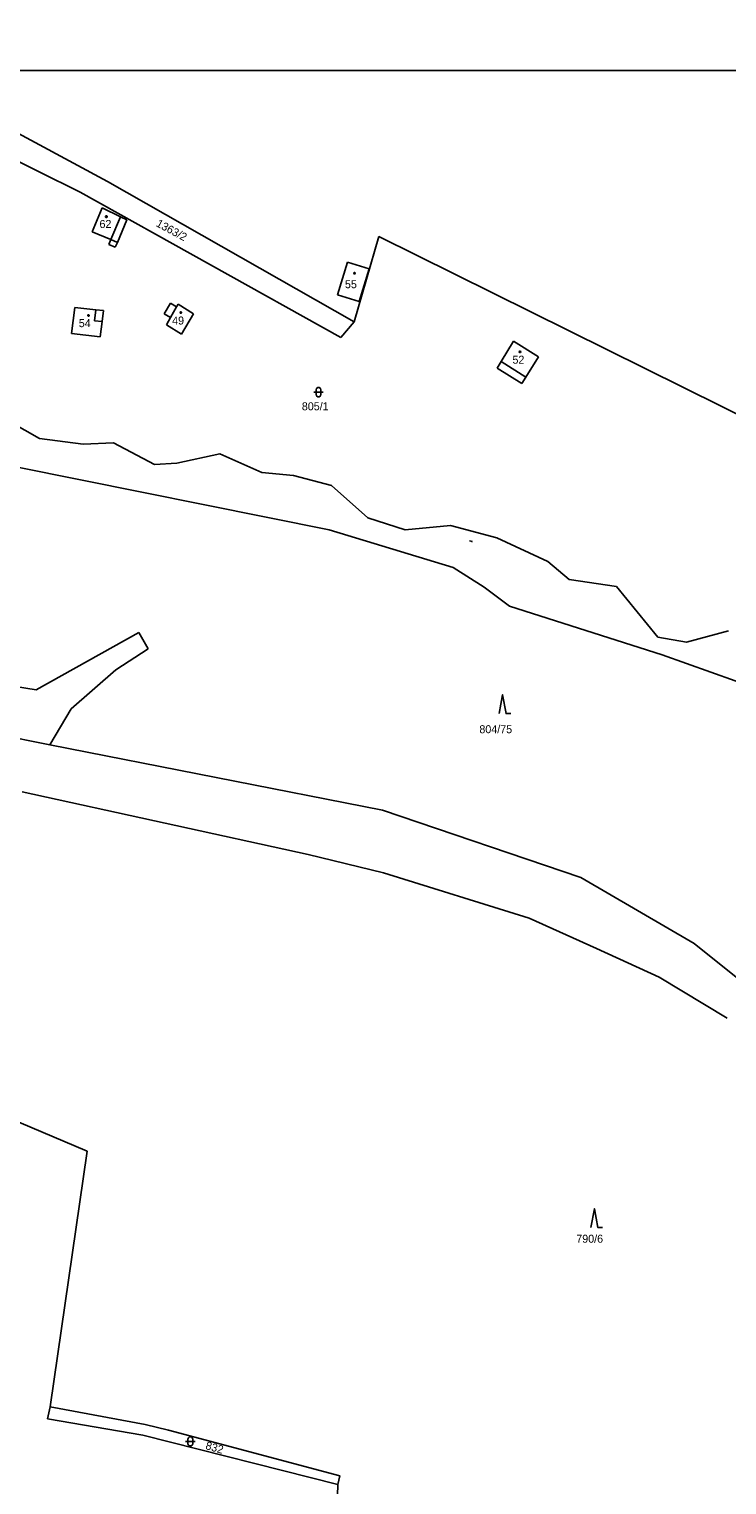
# Model space of a CAD drawing. Extents: x -852001 to -842497, y -1063614 to -1052182.
# Drawn here: x -843807.4 to -843659.2, y -1061876.7 to -1061567.4 of the extents above; entities that cross this region are included whole.
import ezdxf

# ---------------------------------------------------------------- set-up
doc = ezdxf.new("R2010")
doc.units = 0
for name, color, linetype in [('Default', 7, 'Continuous'), ('KN_HRANICE', 7, 'Continuous'), ('KN_KULTURY', 7, 'Continuous'), ('KN_PARCELY', 7, 'Continuous'), ('KN_SLUCKY', 7, 'Continuous'), ('LEGENDA', 7, 'Continuous')]:
    doc.layers.add(name, color=color, linetype=linetype)

# ---------------------------------------------------------------- blocks, each defined once
blk = doc.blocks.new('308')
at = {"layer": 'Default'}
blk.add_lwpolyline([(-0.75, 0), (0, 4), (0.75, 0), (1.75, 0)], dxfattribs=at)
blk = doc.blocks.new('316')
at = {"layer": 'Default'}
for points in [[(-1, 1), (0.27, 1), (1, 1)], [(-0.5, 1.5), (-0.4, 1.79), (-0.15, 1.97), (0.16, 1.97), (0.41, 1.79), (0.51, 1.5), (0.51, 0.5), (0.41, 0.21), (0.16, 0.03), (-0.15, 0.03), (-0.4, 0.21), (-0.5, 0.5), (-0.5, 1.5)]]:
    blk.add_lwpolyline(points, dxfattribs=at)
blk = doc.blocks.new('1060')
at = {"layer": 'Default'}
blk.add_line((-0.3, 0), (0.3, 0), dxfattribs=at)
blk.add_lwpolyline([(0.18, 0.04), (0.3, 0), (0.18, -0.04)], dxfattribs=at)
blk = doc.blocks.new('402')
at = {"layer": 'Default'}
blk.add_lwpolyline([(0.09, 0.15), (0.18, 0), (0.09, -0.15), (-0.09, -0.15), (-0.18, 0), (-0.09, 0.15), (0.09, 0.15)], dxfattribs=at)

msp = doc.modelspace()

# ---------------------------------------------------------------- linework, layer by layer
at = {"layer": 'KN_HRANICE'}
for p, q in [((-843790.75, -1061599.79), (-843825.88, -1061580.84)), ((-843790.75, -1061599.79), (-843825.88, -1061580.84)), ((-843796.57, -1061602.04), (-843829.99, -1061585.51)), ((-843796.57, -1061602.04), (-843829.99, -1061585.51)), ((-843738.36, -1061629.63), (-843790.75, -1061599.79)), ((-843738.36, -1061629.63), (-843790.75, -1061599.79)), ((-843741.22, -1061632.91), (-843796.57, -1061602.04)), ((-843741.22, -1061632.91), (-843796.57, -1061602.04)), ((-843791.86, -1061605.4), (-843794.02, -1061610.48)), ((-843791.86, -1061605.4), (-843794.02, -1061610.48)), ((-843787.99, -1061607.29), (-843791.86, -1061605.4)), ((-843787.99, -1061607.29), (-843791.86, -1061605.4)), ((-843786.62, -1061607.96), (-843787.99, -1061607.29)), ((-843786.62, -1061607.96), (-843787.99, -1061607.29)), ((-843794.02, -1061610.48), (-843790.06, -1061612.14)), ((-843794.02, -1061610.48), (-843790.06, -1061612.14)), ((-843788.66, -1061612.73), (-843786.62, -1061607.96)), ((-843788.66, -1061612.73), (-843786.62, -1061607.96)), ((-843790.49, -1061613.17), (-843790.06, -1061612.14)), ((-843790.49, -1061613.17), (-843790.06, -1061612.14)), ((-843789.09, -1061613.75), (-843790.49, -1061613.17)), ((-843789.09, -1061613.75), (-843790.49, -1061613.17)), ((-843788.66, -1061612.73), (-843789.09, -1061613.75)), ((-843788.66, -1061612.73), (-843789.09, -1061613.75)), ((-843738.36, -1061629.63), (-843733.15, -1061611.51)), ((-843738.36, -1061629.63), (-843733.15, -1061611.51)), ((-843733.15, -1061611.51), (-843581.94, -1061686.41)), ((-843733.15, -1061611.51), (-843581.94, -1061686.41)), ((-843739.78, -1061616.97), (-843741.91, -1061623.89)), ((-843739.78, -1061616.97), (-843741.91, -1061623.89)), ((-843735.17, -1061618.38), (-843739.78, -1061616.97)), ((-843735.17, -1061618.38), (-843739.78, -1061616.97)), ((-843737.3, -1061625.27), (-843735.17, -1061618.38)), ((-843737.3, -1061625.27), (-843735.17, -1061618.38)), ((-843778.7, -1061627.88), (-843777.35, -1061625.62)), ((-843778.7, -1061627.88), (-843777.35, -1061625.62)), ((-843777.35, -1061625.62), (-843776.08, -1061626.44)), ((-843777.35, -1061625.62), (-843776.08, -1061626.44)), ((-843776.08, -1061626.44), (-843775.77, -1061625.89)), ((-843776.08, -1061626.44), (-843775.77, -1061625.89)), ((-843772.46, -1061627.93), (-843775.77, -1061625.89)), ((-843772.46, -1061627.93), (-843775.77, -1061625.89)), ((-843741.91, -1061623.89), (-843737.3, -1061625.27)), ((-843741.91, -1061623.89), (-843737.3, -1061625.27)), ((-843797.7, -1061626.55), (-843798.4, -1061632.11)), ((-843797.7, -1061626.55), (-843798.4, -1061632.11)), ((-843793.25, -1061627.06), (-843797.7, -1061626.55)), ((-843793.25, -1061627.06), (-843797.7, -1061626.55)), ((-843791.58, -1061627.21), (-843793.25, -1061627.06)), ((-843791.58, -1061627.21), (-843793.25, -1061627.06)), ((-843792.32, -1061632.83), (-843791.89, -1061629.54)), ((-843792.32, -1061632.83), (-843791.89, -1061629.54)), ((-843791.89, -1061629.54), (-843791.58, -1061627.21)), ((-843791.89, -1061629.54), (-843791.58, -1061627.21)), ((-843777.36, -1061628.7), (-843778.7, -1061627.88)), ((-843777.36, -1061628.7), (-843778.7, -1061627.88)), ((-843778.23, -1061630.23), (-843777.36, -1061628.7)), ((-843778.23, -1061630.23), (-843777.36, -1061628.7)), ((-843775.02, -1061632.26), (-843772.46, -1061627.93)), ((-843775.02, -1061632.26), (-843772.46, -1061627.93)), ((-843798.4, -1061632.11), (-843792.32, -1061632.83)), ((-843798.4, -1061632.11), (-843792.32, -1061632.83)), ((-843778.23, -1061630.23), (-843775.02, -1061632.26)), ((-843778.23, -1061630.23), (-843775.02, -1061632.26)), ((-843738.36, -1061629.63), (-843741.22, -1061632.91)), ((-843738.36, -1061629.63), (-843741.22, -1061632.91)), ((-843704.5, -1061633.74), (-843707.14, -1061638.06)), ((-843704.5, -1061633.74), (-843707.14, -1061638.06)), ((-843699.21, -1061637.01), (-843704.5, -1061633.74)), ((-843699.21, -1061637.01), (-843704.5, -1061633.74)), ((-843707.14, -1061638.06), (-843708.01, -1061639.48)), ((-843707.14, -1061638.06), (-843708.01, -1061639.48)), ((-843699.21, -1061637.01), (-843701.9, -1061641.36)), ((-843699.21, -1061637.01), (-843701.9, -1061641.36)), ((-843708.01, -1061639.48), (-843702.77, -1061642.74)), ((-843708.01, -1061639.48), (-843702.77, -1061642.74)), ((-843701.9, -1061641.36), (-843702.77, -1061642.74)), ((-843701.9, -1061641.36), (-843702.77, -1061642.74)), ((-843743.69, -1061673.8), (-843809.84, -1061660.45)), ((-843743.69, -1061673.8), (-843809.84, -1061660.45)), ((-843717.35, -1061681.81), (-843743.69, -1061673.8)), ((-843717.35, -1061681.81), (-843743.69, -1061673.8)), ((-843710.75, -1061685.97), (-843717.35, -1061681.81)), ((-843710.75, -1061685.97), (-843717.35, -1061681.81)), ((-843705.34, -1061689.98), (-843710.75, -1061685.97)), ((-843705.34, -1061689.98), (-843710.75, -1061685.97)), ((-843672.91, -1061700.32), (-843705.34, -1061689.98)), ((-843672.91, -1061700.32), (-843705.34, -1061689.98)), ((-843805.91, -1061707.81), (-843784.1, -1061695.61)), ((-843805.91, -1061707.81), (-843784.1, -1061695.61)), ((-843784.1, -1061695.61), (-843782.09, -1061699.05)), ((-843784.1, -1061695.61), (-843782.09, -1061699.05)), ((-843782.09, -1061699.05), (-843788.98, -1061703.5)), ((-843782.09, -1061699.05), (-843788.98, -1061703.5)), ((-843610.42, -1061722.69), (-843672.91, -1061700.32)), ((-843610.42, -1061722.69), (-843672.91, -1061700.32)), ((-843788.98, -1061703.5), (-843798.45, -1061711.83)), ((-843788.98, -1061703.5), (-843798.45, -1061711.83)), ((-843818.83, -1061705.66), (-843805.91, -1061707.81)), ((-843818.83, -1061705.66), (-843805.91, -1061707.81)), ((-843798.45, -1061711.83), (-843803.02, -1061719.45)), ((-843798.45, -1061711.83), (-843803.02, -1061719.45)), ((-843803.02, -1061719.45), (-843833.57, -1061713.26)), ((-843803.02, -1061719.45), (-843833.57, -1061713.26)), ((-843732.34, -1061733.36), (-843803.02, -1061719.45)), ((-843732.34, -1061733.36), (-843803.02, -1061719.45)), ((-843808.89, -1061729.47), (-843748.15, -1061742.74)), ((-843808.89, -1061729.47), (-843748.15, -1061742.74)), ((-843690.18, -1061747.67), (-843732.34, -1061733.36)), ((-843690.18, -1061747.67), (-843732.34, -1061733.36)), ((-843748.15, -1061742.74), (-843732.13, -1061746.69)), ((-843748.15, -1061742.74), (-843732.13, -1061746.69)), ((-843732.13, -1061746.69), (-843701.21, -1061756.3)), ((-843732.13, -1061746.69), (-843701.21, -1061756.3)), ((-843666.11, -1061761.68), (-843690.18, -1061747.67)), ((-843666.11, -1061761.68), (-843690.18, -1061747.67)), ((-843701.21, -1061756.3), (-843686.91, -1061762.71)), ((-843701.21, -1061756.3), (-843686.91, -1061762.71)), ((-843652.18, -1061772.88), (-843666.11, -1061761.68)), ((-843652.18, -1061772.88), (-843666.11, -1061761.68)), ((-843686.91, -1061762.71), (-843673.54, -1061768.81)), ((-843686.91, -1061762.71), (-843673.54, -1061768.81)), ((-843673.54, -1061768.81), (-843659.13, -1061777.56)), ((-843673.54, -1061768.81), (-843659.13, -1061777.56)), ((-843795.06, -1061805.75), (-843847.5, -1061783.54)), ((-843795.06, -1061805.75), (-843847.5, -1061783.54)), ((-843802.94, -1061860.1), (-843795.06, -1061805.75)), ((-843802.94, -1061860.1), (-843795.06, -1061805.75)), ((-843802.94, -1061860.1), (-843803.53, -1061862.65)), ((-843802.94, -1061860.1), (-843803.53, -1061862.65)), ((-843782.76, -1061863.82), (-843802.94, -1061860.1)), ((-843782.76, -1061863.82), (-843802.94, -1061860.1)), ((-843803.53, -1061862.65), (-843783.27, -1061866.08)), ((-843803.53, -1061862.65), (-843783.27, -1061866.08)), ((-843777.81, -1061865.06), (-843782.76, -1061863.82)), ((-843777.81, -1061865.06), (-843782.76, -1061863.82)), ((-843783.27, -1061866.08), (-843741.79, -1061876.62)), ((-843783.27, -1061866.08), (-843741.79, -1061876.62)), ((-843741.39, -1061874.76), (-843777.81, -1061865.06)), ((-843741.39, -1061874.76), (-843777.81, -1061865.06)), ((-843741.79, -1061876.62), (-843743.62, -1061923)), ((-843741.79, -1061876.62), (-843743.62, -1061923)), ((-843741.39, -1061874.76), (-843741.79, -1061876.62)), ((-843741.39, -1061874.76), (-843741.79, -1061876.62))]:
    msp.add_line(p, q, dxfattribs=at)
at = {"layer": 'KN_SLUCKY'}
for p, q in [((-843787.99, -1061607.29), (-843790.06, -1061612.14)), ((-843787.99, -1061607.29), (-843790.06, -1061612.14)), ((-843790.06, -1061612.14), (-843788.66, -1061612.73)), ((-843790.06, -1061612.14), (-843788.66, -1061612.73)), ((-843776.08, -1061626.44), (-843777.36, -1061628.7)), ((-843776.08, -1061626.44), (-843777.36, -1061628.7)), ((-843793.53, -1061629.37), (-843793.25, -1061627.06)), ((-843793.53, -1061629.37), (-843793.25, -1061627.06)), ((-843791.89, -1061629.54), (-843793.53, -1061629.37)), ((-843791.89, -1061629.54), (-843793.53, -1061629.37)), ((-843701.9, -1061641.36), (-843707.14, -1061638.06)), ((-843701.9, -1061641.36), (-843707.14, -1061638.06)), ((-843811.41, -1061650.87), (-843805.17, -1061654.37)), ((-843811.41, -1061650.87), (-843805.17, -1061654.37)), ((-843805.17, -1061654.37), (-843795.89, -1061655.59)), ((-843805.17, -1061654.37), (-843795.89, -1061655.59)), ((-843795.89, -1061655.59), (-843789.5, -1061655.29)), ((-843795.89, -1061655.59), (-843789.5, -1061655.29)), ((-843789.5, -1061655.29), (-843780.76, -1061659.95)), ((-843789.5, -1061655.29), (-843780.76, -1061659.95)), ((-843780.76, -1061659.95), (-843776.04, -1061659.65)), ((-843780.76, -1061659.95), (-843776.04, -1061659.65)), ((-843776.04, -1061659.65), (-843766.91, -1061657.67)), ((-843776.04, -1061659.65), (-843766.91, -1061657.67)), ((-843766.91, -1061657.67), (-843757.94, -1061661.63)), ((-843766.91, -1061657.67), (-843757.94, -1061661.63)), ((-843757.94, -1061661.63), (-843751.24, -1061662.24)), ((-843757.94, -1061661.63), (-843751.24, -1061662.24)), ((-843751.24, -1061662.24), (-843743.18, -1061664.37)), ((-843751.24, -1061662.24), (-843743.18, -1061664.37)), ((-843743.18, -1061664.37), (-843735.42, -1061671.22)), ((-843743.18, -1061664.37), (-843735.42, -1061671.22)), ((-843735.42, -1061671.22), (-843727.51, -1061673.81)), ((-843735.42, -1061671.22), (-843727.51, -1061673.81)), ((-843727.51, -1061673.81), (-843717.92, -1061672.89)), ((-843727.51, -1061673.81), (-843717.92, -1061672.89)), ((-843717.92, -1061672.89), (-843708.03, -1061675.48)), ((-843717.92, -1061672.89), (-843708.03, -1061675.48)), ((-843708.03, -1061675.48), (-843697.23, -1061680.5)), ((-843708.03, -1061675.48), (-843697.23, -1061680.5)), ((-843697.23, -1061680.5), (-843692.66, -1061684.31)), ((-843697.23, -1061680.5), (-843692.66, -1061684.31)), ((-843692.66, -1061684.31), (-843682.62, -1061685.83)), ((-843692.66, -1061684.31), (-843682.62, -1061685.83)), ((-843682.62, -1061685.83), (-843673.87, -1061696.6)), ((-843682.62, -1061685.83), (-843673.87, -1061696.6)), ((-843673.87, -1061696.6), (-843667.79, -1061697.67)), ((-843673.87, -1061696.6), (-843667.79, -1061697.67)), ((-843667.79, -1061697.67), (-843658.81, -1061695.23)), ((-843667.79, -1061697.67), (-843658.81, -1061695.23))]:
    msp.add_line(p, q, dxfattribs=at)
at = {"layer": 'LEGENDA'}
msp.add_lwpolyline([(-843931.33, -1061576.22), (-843337.33, -1061576.22), (-843337.33, -1061156.22), (-843931.33, -1061156.22)], close=True, dxfattribs=at)

# ---------------------------------------------------------------- block references
at = {"layer": 'KN_KULTURY'}
for name, p in [('402', (-843791, -1061607.27)), ('402', (-843791, -1061607.27)), ('402', (-843738.3, -1061619.29)), ('402', (-843738.3, -1061619.29)), ('402', (-843794.79, -1061628.25)), ('402', (-843794.79, -1061628.25)), ('402', (-843775.17, -1061627.65)), ('402', (-843775.17, -1061627.65)), ('402', (-843703.14, -1061635.99)), ('402', (-843703.14, -1061635.99)), ('316', (-843745.93, -1061645.55)), ('316', (-843745.93, -1061645.55)), ('308', (-843706.82, -1061712.83)), ('308', (-843706.82, -1061712.83)), ('308', (-843687.34, -1061822.02)), ('308', (-843687.34, -1061822.02)), ('316', (-843773.16, -1061868.43)), ('316', (-843773.16, -1061868.43))]:
    msp.add_blockref(name, p, dxfattribs=at)
at = {"layer": 'KN_PARCELY', "rotation": -16.855576}
msp.add_blockref('1060', (-843713.59, -1061676.22), dxfattribs=at)
msp.add_blockref('1060', (-843713.59, -1061676.22), dxfattribs=at)

# ---------------------------------------------------------------- texts
at = {"layer": 'KN_PARCELY'}
for s, p in [('62', (-843792.45, -1061609.68)), ('62', (-843792.45, -1061609.68)), ('55', (-843740.31, -1061622.47)), ('55', (-843740.31, -1061622.47)), ('54', (-843796.85, -1061630.74)), ('54', (-843796.85, -1061630.74)), ('49', (-843777.02, -1061630.18)), ('49', (-843777.02, -1061630.18)), ('52', (-843704.73, -1061638.51)), ('52', (-843704.73, -1061638.51)), ('805/1', (-843749.47, -1061648.4)), ('805/1', (-843749.47, -1061648.4)), ('804/75', (-843711.76, -1061717)), ('804/75', (-843711.76, -1061717)), ('790/6', (-843691.17, -1061825.23)), ('790/6', (-843691.17, -1061825.23))]:
    msp.add_text(s, height=1.7, dxfattribs=at).set_placement(p)
for s, rotation, p in [('1363/2', 331.628, (-843780.58, -1061609.22)), ('1363/2', 331.628, (-843780.58, -1061609.22)), ('832', 343.947, (-843770.06, -1061869.03)), ('832', 343.947, (-843770.06, -1061869.03))]:
    msp.add_text(s, height=1.7, rotation=rotation, dxfattribs=at).set_placement(p)

doc.saveas('drawing.dxf')
